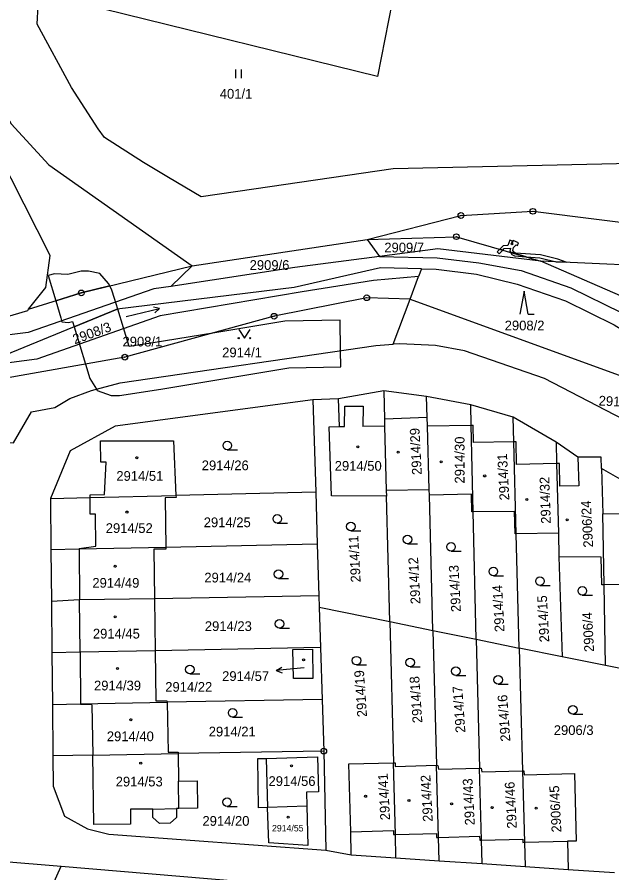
# Model space of a CAD drawing. Extents: x -644096 to -634268, y -1141430 to -1133463.
# Drawn here: x -640132.5 to -640028.5, y -1138278.2 to -1138128.6 of the extents above; entities that cross this region are included whole.
import ezdxf

# ---------------------------------------------------------------- set-up
doc = ezdxf.new("R2010")
doc.units = 0
for name, color, linetype in [('_CIVIL_CONSTRUCTION', 7, 'Continuous'), ('B_Hranice _3D', 7, 'Continuous'), ('M_Svah_Nasyp', 7, 'Continuous'), ('M_Svah_Zarez', 7, 'Continuous'), ('spodek_zarez', 7, 'Continuous'), ('svrsek_osa_sjezdy', 7, 'Continuous'), ('svrsek_osa_VRT', 7, 'Continuous'), ('svrsek_popisy_VRT', 7, 'Continuous'), ('terminal_VRT', 7, 'Continuous')]:
    doc.layers.add(name, color=color, linetype=linetype)

msp = doc.modelspace()

# ---------------------------------------------------------------- linework, layer by layer
at = {"layer": '_CIVIL_CONSTRUCTION'}
for centre, radius in [((-640054.9, -1138163.28), 0.5), ((-640042.31, -1138162.55), 0.5), ((-640042.31, -1138162.55), 0.0303), ((-640054.9, -1138163.28), 0.0303), ((-640055.7, -1138166.98), 0.5), ((-640055.7, -1138166.98), 0.0303), ((-640121.25, -1138176.81), 0.5), ((-640121.25, -1138176.81), 0.0303), ((-640071.36, -1138177.65), 0.5), ((-640071.36, -1138177.65), 0.0303), ((-640087.56, -1138180.89), 0.5), ((-640087.56, -1138180.89), 0.0303), ((-640113.65, -1138188.05), 0.5), ((-640113.65, -1138188.05), 0.0303), ((-640078.88, -1138256.92), 0.5), ((-640078.88, -1138256.92), 0.0303)]:
    msp.add_circle(centre, radius, dxfattribs=at)
at = {"layer": 'B_Hranice _3D'}
for points in [[(-640047.54, -1138168.57), (-640048.12, -1138169.17), (-640047.58, -1138169.32), (-640047.32, -1138169.05), (-640046.26, -1138168.98), (-640046.38, -1138169.52), (-640046.25, -1138169.71), (-640043.5, -1138170.5), (-640041.09, -1138170.68), (-640038.27, -1138171.36), (-640036.52, -1138171.44), (-640037.98, -1138170.92), (-640041.01, -1138170.18), (-640045.38, -1138169.86), (-640045.64, -1138169.7), (-640045.84, -1138169.4), (-640045.72, -1138168.85), (-640045.22, -1138168.43), (-640045.02, -1138168.52), (-640044.82, -1138168.06), (-640045.74, -1138167.66), (-640045.94, -1138168.12), (-640045.74, -1138168.21), (-640045.95, -1138168.39), (-640046.09, -1138168.28), (-640045.9, -1138167.79), (-640046.36, -1138167.61), (-640046.72, -1138168.51)], [(-640048.56, -1138169.63), (-640048.2, -1138169.97), (-640047.58, -1138169.32), (-640048.12, -1138169.17)], [(-640046.25, -1138169.71), (-640045.99, -1138170.07), (-640045.54, -1138170.35), (-640043.5, -1138170.5)], [(-640125.72, -1138178.2), (-640121.25, -1138176.81), (-640116.26, -1138175.59), (-640116.47, -1138175.15), (-640118, -1138173.44), (-640119.97, -1138172.99), (-640121.25, -1138172.99), (-640123.63, -1138173.58), (-640125.93, -1138173.45), (-640127.02, -1138173.76)], [(-640125.72, -1138178.2), (-640124.85, -1138181.16), (-640124.64, -1138181.89), (-640123.51, -1138181.98), (-640122.79, -1138181.8), (-640122.5, -1138182.77), (-640114.96, -1138179.68), (-640114.89, -1138179.67), (-640115.47, -1138177.78), (-640115.92, -1138176.32), (-640116.26, -1138175.59), (-640121.25, -1138176.81)], [(-640107.37, -1138193.62), (-640084.96, -1138189.92), (-640075.87, -1138189.76), (-640075.92, -1138186.9), (-640076.01, -1138181.58), (-640085.7, -1138181.76), (-640098.26, -1138183.83), (-640108.67, -1138185.54), (-640112.89, -1138186.21), (-640114.89, -1138179.67), (-640114.96, -1138179.68), (-640122.5, -1138182.77), (-640120.51, -1138189.27), (-640119.74, -1138191.8), (-640118.61, -1138193.62), (-640118.46, -1138193.86), (-640116.06, -1138194.76), (-640114.58, -1138194.76)]]:
    msp.add_lwpolyline(points, close=True, dxfattribs=at)
at = {"layer": 'M_Svah_Nasyp'}
for p, q in [((-640075.27, -1138200.17), (-640075.17, -1138196.61)), ((-640075.17, -1138196.61), (-640071.97, -1138196.59)), ((-640071.97, -1138196.59), (-640072.05, -1138200.14)), ((-640060.8, -1138198.57), (-640068.26, -1138198.9)), ((-640076.15, -1138200.18), (-640075.27, -1138200.17)), ((-640068.23, -1138200.1), (-640072.05, -1138200.14)), ((-640060.74, -1138200.07), (-640053.09, -1138199.95)), ((-640053.09, -1138199.95), (-640052.74, -1138199.94)), ((-640052.72, -1138202.98), (-640052.74, -1138199.94)), ((-640045.67, -1138202.84), (-640052.72, -1138202.98)), ((-640045.23, -1138202.83), (-640045.67, -1138202.84)), ((-640045.2, -1138206.83), (-640045.23, -1138202.83)), ((-640034.45, -1138205.52), (-640034.3, -1138210.54)), ((-640038.17, -1138206.63), (-640045.2, -1138206.83)), ((-640037.66, -1138206.62), (-640038.17, -1138206.63)), ((-640037.6, -1138210.57), (-640037.66, -1138206.62)), ((-640034.3, -1138210.54), (-640037.6, -1138210.57)), ((-640119.68, -1138215.48), (-640119.71, -1138212.58)), ((-640118.77, -1138215.47), (-640119.68, -1138215.48)), ((-640118.72, -1138221.1), (-640118.77, -1138215.47)), ((-640121.63, -1138221.48), (-640118.72, -1138221.1)), ((-640121.63, -1138221.48), (-640121.63, -1138221.63)), ((-640121.63, -1138221.63), (-640121.55, -1138230.49)), ((-640121.47, -1138239.64), (-640121.55, -1138230.49)), ((-640121.47, -1138239.64), (-640121.39, -1138248.65)), ((-640121.39, -1138248.79), (-640121.39, -1138248.65)), ((-640119.42, -1138248.8), (-640121.39, -1138248.79)), ((-640119.42, -1138248.8), (-640119.25, -1138257.62)), ((-640088.95, -1138258.18), (-640088.7, -1138266.77)), ((-640104.23, -1138266.94), (-640104.28, -1138262.19)), ((-640108.76, -1138267.04), (-640104.61, -1138266.97)), ((-640074.17, -1138271.02), (-640066.67, -1138270.8)), ((-640066.67, -1138270.8), (-640066.67, -1138271.5)), ((-640066.67, -1138271.5), (-640066.36, -1138271.49)), ((-640066.36, -1138271.49), (-640059.17, -1138271.29)), ((-640059.17, -1138271.29), (-640059.18, -1138272)), ((-640059.18, -1138272), (-640058.84, -1138271.99)), ((-640058.84, -1138271.99), (-640051.65, -1138271.8)), ((-640051.65, -1138271.8), (-640051.59, -1138272.49)), ((-640051.59, -1138272.49), (-640051.31, -1138272.48)), ((-640051.31, -1138272.48), (-640044.07, -1138272.31)), ((-640044.07, -1138272.31), (-640044.06, -1138272.87)), ((-640044.06, -1138272.87), (-640043.8, -1138272.85)), ((-640043.8, -1138272.85), (-640036.3, -1138272.68))]:
    msp.add_line(p, q, dxfattribs=at)
at = {"layer": 'M_Svah_Zarez'}
for centre in [(-640072.92, -1138203.72), (-640065.85, -1138204.67), (-640111.53, -1138205.62), (-640058.35, -1138206.33), (-640050.75, -1138208.82), (-640043.39, -1138212.91), (-640113.27, -1138215.12), (-640036.34, -1138216.47), (-640115.33, -1138224.61), (-640115.33, -1138233.43), (-640082.39, -1138240.94), (-640114.93, -1138242.46), (-640112.61, -1138251.42), (-640110.87, -1138259.03), (-640084.5, -1138259.5), (-640071.55, -1138264.82), (-640063.98, -1138265.56), (-640056.52, -1138266.12), (-640049.45, -1138266.8), (-640041.77, -1138266.91), (-640085.08, -1138268.46)]:
    msp.add_circle(centre, 0.175, dxfattribs=at)
at = {"layer": 'spodek_zarez'}
msp.add_circle((-638683.07, -1137056.85), 1378.08, dxfattribs=at)
at = {"layer": 'svrsek_osa_sjezdy'}
for p, q in [((-640094.25, -1138139.27), (-640094.25, -1138137.77)), ((-640093.25, -1138139.27), (-640093.25, -1138137.77)), ((-640043.87, -1138176.51), (-640044.62, -1138180.51)), ((-640043.12, -1138180.51), (-640043.87, -1138176.51)), ((-640107.57, -1138179.56), (-640108.63, -1138179.29)), ((-640113.41, -1138180.91), (-640107.57, -1138179.56)), ((-640107.57, -1138179.56), (-640108.41, -1138180.27)), ((-640043.12, -1138180.51), (-640042.12, -1138180.51)), ((-640095.73, -1138204.24), (-640093.98, -1138204.24)), ((-640086.99, -1138217.07), (-640085.24, -1138217.07)), ((-640074.15, -1138218.38), (-640072.4, -1138218.38)), ((-640064.24, -1138220.67), (-640062.49, -1138220.67)), ((-640056.63, -1138221.94), (-640054.88, -1138221.94)), ((-640086.79, -1138226.73), (-640085.04, -1138226.73)), ((-640049.23, -1138226.28), (-640047.48, -1138226.28)), ((-640041.08, -1138227.97), (-640039.33, -1138227.97)), ((-640033.68, -1138229.66), (-640031.93, -1138229.66)), ((-640086.59, -1138235.41), (-640084.84, -1138235.41)), ((-640073.16, -1138241.85), (-640071.41, -1138241.85)), ((-640063.78, -1138242.16), (-640062.03, -1138242.16)), ((-640102.28, -1138243.41), (-640100.53, -1138243.41)), ((-640055.81, -1138243.68), (-640054.06, -1138243.68)), ((-640048.41, -1138245.21), (-640046.66, -1138245.21)), ((-640094.8, -1138250.97), (-640093.05, -1138250.97)), ((-640035.34, -1138250.47), (-640033.59, -1138250.47)), ((-640095.78, -1138266.59), (-640094.03, -1138266.59))]:
    msp.add_line(p, q, dxfattribs=at)
msp.add_lwpolyline([(-640093.74, -1138183.23), (-640092.74, -1138184.73), (-640091.74, -1138183.23)], dxfattribs=at)
for centre, radius in [((-640093.74, -1138184.73), 0.1), ((-640091.74, -1138184.73), 0.1), ((-640095.73, -1138203.49), 0.75), ((-640086.99, -1138216.32), 0.75), ((-640074.15, -1138217.63), 0.75), ((-640064.24, -1138219.92), 0.75), ((-640056.63, -1138221.19), 0.75), ((-640086.79, -1138225.98), 0.75), ((-640049.23, -1138225.53), 0.75), ((-640041.08, -1138227.22), 0.75), ((-640033.68, -1138228.91), 0.75), ((-640086.59, -1138234.66), 0.75), ((-640073.16, -1138241.1), 0.75), ((-640063.78, -1138241.41), 0.75), ((-640102.28, -1138242.66), 0.75), ((-640055.81, -1138242.93), 0.75), ((-640048.41, -1138244.46), 0.75), ((-640094.8, -1138250.22), 0.75), ((-640035.34, -1138249.72), 0.75), ((-640095.78, -1138265.84), 0.75)]:
    msp.add_circle(centre, radius, dxfattribs=at)
at = {"layer": 'svrsek_popisy_VRT'}
for p, q in [((-640087.17, -1138242.85), (-640086.22, -1138242.25)), ((-640084.18, -1138242.54), (-640087.17, -1138242.85)), ((-640087.17, -1138242.85), (-640086.12, -1138243.25)), ((-640082.31, -1138242.35), (-640084.18, -1138242.54))]:
    msp.add_line(p, q, dxfattribs=at)
at = {"layer": 'terminal_VRT'}
for p, q in [((-640101.86, -1138172.06), (-640071.28, -1138167.46)), ((-640071.28, -1138167.46), (-640069.11, -1138170.45)), ((-640101.86, -1138172.06), (-640105.62, -1138175.67)), ((-640061.8, -1138172.6), (-640068.96, -1138172.45)), ((-640061.8, -1138172.6), (-640062.3, -1138173.93)), ((-640062.3, -1138173.93), (-640070.2, -1138174.64)), ((-640063.78, -1138177.89), (-640062.3, -1138173.93)), ((-640066.74, -1138185.8), (-640063.78, -1138177.89)), ((-640063.78, -1138177.89), (-640025.5, -1138191.85)), ((-640068.39, -1138193.94), (-640076.3, -1138195.32)), ((-640060.89, -1138194.94), (-640068.39, -1138193.94)), ((-640076.3, -1138195.32), (-640080.78, -1138195.53)), ((-640080.78, -1138195.53), (-640080.28, -1138211.67)), ((-640053.17, -1138196.36), (-640060.89, -1138194.94)), ((-640045.78, -1138198.51), (-640053.17, -1138196.36)), ((-640038.26, -1138202.9), (-640045.78, -1138198.51)), ((-640030.32, -1138207.49), (-640030.1, -1138215.44)), ((-640008.99, -1138219.81), (-640030.32, -1138207.49)), ((-640119.71, -1138212.58), (-640104.71, -1138212.23)), ((-640080.28, -1138211.67), (-640104.71, -1138212.23)), ((-640080.28, -1138211.67), (-640080, -1138220.72)), ((-640060.47, -1138211.26), (-640067.94, -1138211.35)), ((-640067.94, -1138211.35), (-640067.91, -1138212.35)), ((-640067.34, -1138234.28), (-640067.91, -1138212.35)), ((-640060.4, -1138212.17), (-640060.47, -1138211.26)), ((-640059.79, -1138235.82), (-640060.4, -1138212.17)), ((-640126.64, -1138212.74), (-640119.71, -1138212.58)), ((-640126.64, -1138212.74), (-640126.55, -1138221.74)), ((-640052.26, -1138237.35), (-640052.75, -1138215.1)), ((-640029.89, -1138227.85), (-640030.1, -1138215.44)), ((-640037.86, -1138218.81), (-640045.25, -1138218.92)), ((-640044.73, -1138238.89), (-640045.25, -1138218.92)), ((-640037.86, -1138218.81), (-640037.77, -1138222.97)), ((-640080, -1138220.72), (-640106.49, -1138221.3)), ((-640080, -1138220.72), (-640079.72, -1138229.77)), ((-640126.55, -1138221.74), (-640126.47, -1138230.74)), ((-640037.77, -1138222.97), (-640037.19, -1138240.42)), ((-640029.65, -1138241.96), (-640029.89, -1138227.85)), ((-640079.72, -1138229.77), (-640108.46, -1138230.31)), ((-640079.72, -1138229.77), (-640079.66, -1138231.78)), ((-640126.47, -1138230.74), (-640126.38, -1138239.74)), ((-640108.46, -1138230.31), (-640108.35, -1138239.39)), ((-640079.66, -1138231.78), (-640067.34, -1138234.28)), ((-640079.66, -1138231.78), (-640079.44, -1138238.82)), ((-640067.34, -1138234.28), (-640066.69, -1138258.96)), ((-640067.34, -1138234.28), (-640059.79, -1138235.82)), ((-640059.79, -1138235.82), (-640052.26, -1138237.35)), ((-640059.79, -1138235.82), (-640059.17, -1138259.4)), ((-640052.26, -1138237.35), (-640044.73, -1138238.89)), ((-640052.26, -1138237.35), (-640051.65, -1138259.91)), ((-640079.44, -1138238.82), (-640108.35, -1138239.39)), ((-640079.44, -1138238.82), (-640079.16, -1138247.87)), ((-640037.19, -1138240.42), (-640044.73, -1138238.89)), ((-640044.73, -1138238.89), (-640044.14, -1138260.35)), ((-640126.38, -1138239.74), (-640126.3, -1138248.74)), ((-640029.65, -1138241.96), (-640037.19, -1138240.42)), ((-640022.84, -1138243.35), (-640029.65, -1138241.96)), ((-640079.16, -1138247.87), (-640106.27, -1138248.37)), ((-640079.16, -1138247.87), (-640078.88, -1138256.92)), ((-640126.3, -1138248.74), (-640126.21, -1138257.74)), ((-640078.88, -1138256.92), (-640104.34, -1138257.34)), ((-640078.88, -1138256.92), (-640078.52, -1138274.23)), ((-640119.25, -1138257.62), (-640126.21, -1138257.74)), ((-640119.25, -1138257.62), (-640104.34, -1138257.34)), ((-640081.82, -1138266.53), (-640088.7, -1138266.77)), ((-640078.52, -1138274.23), (-640074.07, -1138275.04)), ((-640074.07, -1138275.04), (-640066.25, -1138275.57)), ((-640066.25, -1138275.57), (-640058.73, -1138276.08)), ((-640058.73, -1138276.08), (-640051.2, -1138276.59)), ((-640051.2, -1138276.59), (-640043.68, -1138277.1)), ((-640124.76, -1138277.05), (-640083.27, -1138280.51)), ((-640043.68, -1138277.1), (-640036.16, -1138277.6)), ((-640036.16, -1138277.6), (-640028.04, -1138278.15))]:
    msp.add_line(p, q, dxfattribs=at)
for points in [[(-639964.57, -1138155.72), (-639970.93, -1138156.51), (-639981.92, -1138158.02), (-640012.66, -1138153.48), (-640025.08, -1138154.19), (-640066.74, -1138155.12), (-640091.07, -1138158.68), (-640100.29, -1138160), (-640106.04, -1138156.61), (-640110.39, -1138154.04), (-640117.22, -1138149.62), (-640118.33, -1138148.11), (-640122.99, -1138140.9), (-640128.97, -1138129.83), (-640128.12, -1138113.45), (-640129.91, -1138106.89), (-640135.07, -1138095.63), (-640136.46, -1138093.31)], [(-640125.7, -1138099.66), (-640125.1, -1138103.21), (-640122.95, -1138109.83), (-640120.35, -1138113.31), (-640115.86, -1138115), (-640114.4, -1138107.51), (-640065.64, -1138119.33), (-640069.46, -1138138.97), (-640117.31, -1138127.21), (-640116, -1138120.49), (-640123.3, -1138118.01), (-640129.85, -1138099.16), (-640131.13, -1138096.38)], [(-640269.74, -1138181.24), (-640284.28, -1138177.7), (-640283.65, -1138163.14), (-640278.43, -1138154.54), (-640260.81, -1138144.4), (-640250.28, -1138126.64), (-640249.95, -1138111.05), (-640244.3, -1138108.64), (-640240.85, -1138108.4), (-640180.48, -1138113.95), (-640156.4, -1138108.35), (-640147.57, -1138118.28), (-640140.23, -1138135.35), (-640133.49, -1138147.23), (-640126.91, -1138154.41), (-640101.86, -1138172.06)], [(-640130.46, -1138179.68), (-640127.48, -1138175.86), (-640126.67, -1138170.26), (-640149.51, -1138125.25), (-640154.45, -1138122.4), (-640159.15, -1138122.47), (-640239.14, -1138123.66), (-640248.63, -1138129.89), (-640258.75, -1138143.28), (-640266, -1138158.68), (-640267.64, -1138164.01), (-640267.29, -1138175.17), (-640266.27, -1138180.09)], [(-640071.28, -1138167.46), (-640054.9, -1138163.28), (-640042.31, -1138162.55), (-639994.57, -1138168.5), (-639967.15, -1138169.36), (-639952.57, -1138168.47), (-639950.23, -1138170.07), (-639941.74, -1138175.48)], [(-640071.28, -1138167.46), (-640055.7, -1138166.98), (-640040.94, -1138171.24)], [(-640069.11, -1138170.45), (-640083.93, -1138172.37), (-640105.62, -1138175.67)], [(-640040.94, -1138171.24), (-640058.94, -1138169.13), (-640069.11, -1138170.45)], [(-640069.11, -1138170.45), (-640059.05, -1138170.66), (-640051.78, -1138171.58), (-640044.37, -1138172.92), (-640035.68, -1138175.94), (-640026.91, -1138180.25), (-640018.62, -1138185.33), (-640008.1, -1138194.3), (-639989.34, -1138210.79), (-639965.8, -1138213.29), (-639950.45, -1138211.57), (-639945.86, -1138213.03), (-639937.34, -1138221.26), (-639936.21, -1138221.49), (-639933.84, -1138221.84), (-639891.59, -1138218.9), (-639875.06, -1138222.44), (-639841.83, -1138231.14), (-639830.5, -1138233.25), (-639820.91, -1138233.83), (-639809.11, -1138234.17), (-639758.74, -1138238.27), (-639748.88, -1138238.87), (-639700.55, -1138249.98)], [(-639944.04, -1138182.89), (-639944.02, -1138179.6), (-639953.15, -1138175.84), (-639964.62, -1138174.37), (-639980.56, -1138175.67), (-640015.24, -1138172.43), (-640040.94, -1138171.24)], [(-639991.53, -1138205.59), (-640001.69, -1138195.34), (-640015.51, -1138183.62), (-640025.66, -1138177.9), (-640040.94, -1138171.24)], [(-640068.96, -1138172.45), (-640084.04, -1138175.86), (-640114.96, -1138179.68), (-640134.56, -1138187.72), (-640175.26, -1138190.33)], [(-640130.46, -1138179.68), (-640121.25, -1138176.81), (-640101.86, -1138172.06)], [(-640061.8, -1138172.6), (-640059.2, -1138172.66), (-640052.15, -1138173.55), (-640045.06, -1138175.27), (-640036.63, -1138178.2), (-640028.09, -1138182.4), (-640020.06, -1138187.32), (-640009.69, -1138196.16), (-639990.18, -1138212.71)], [(-640070.2, -1138174.64), (-640082.65, -1138176.64), (-640107.48, -1138180.83), (-640129.05, -1138188.37), (-640149.86, -1138191.12), (-640169.26, -1138191.54)], [(-640105.62, -1138175.67), (-640108.55, -1138176.11), (-640130.53, -1138183.72), (-640150.56, -1138186.24), (-640169.17, -1138186.77), (-640173.34, -1138185.75), (-640178.15, -1138184.55)], [(-640063.78, -1138177.89), (-640071.36, -1138177.65), (-640087.56, -1138180.89), (-640113.65, -1138188.05), (-640136.4, -1138192.08)], [(-640165.29, -1138182.95), (-640139.5, -1138182.51), (-640130.6, -1138179.86), (-640130.46, -1138179.68)], [(-640136.12, -1138202.84), (-640133.1, -1138203), (-640129.94, -1138197.63), (-640125.85, -1138196.87), (-640123.25, -1138195.28), (-640119.47, -1138193.85), (-640114.48, -1138192.52), (-640069.79, -1138186.01), (-640066.74, -1138185.8)], [(-639993.56, -1138219.33), (-640026.5, -1138198.95), (-640040.31, -1138191.76), (-640054.27, -1138186.91), (-640059.37, -1138186.03), (-640065.6, -1138185.72), (-640066.74, -1138185.8)], [(-640068.39, -1138193.94), (-640068.26, -1138198.9), (-640068.23, -1138200.1), (-640067.94, -1138211.35)], [(-640080.78, -1138195.53), (-640115.31, -1138200.13), (-640123.18, -1138204.41), (-640126.64, -1138212.74)], [(-640067.91, -1138212.35), (-640077.54, -1138212.26), (-640077.94, -1138200.2), (-640076.15, -1138200.18), (-640076.3, -1138195.32)], [(-640060.47, -1138211.26), (-640060.74, -1138200.07), (-640060.8, -1138198.57), (-640060.89, -1138194.94)], [(-640052.75, -1138215.1), (-640053.09, -1138199.95), (-640053.17, -1138196.36)], [(-640045.25, -1138218.92), (-640045.67, -1138202.84), (-640045.78, -1138198.51)], [(-640119.71, -1138212.58), (-640119.72, -1138212.11), (-640117.21, -1138212.04), (-640116.91, -1138206.39), (-640117.82, -1138206.41), (-640117.91, -1138202.7), (-640105.12, -1138202.66), (-640104.71, -1138212.23)], [(-640030.32, -1138207.49), (-640030.37, -1138205.54), (-640034.45, -1138205.52), (-640038.26, -1138202.9)], [(-640038.26, -1138202.9), (-640038.17, -1138206.63), (-640037.86, -1138218.81)], [(-640104.71, -1138212.23), (-640104.7, -1138212.56), (-640106.62, -1138212.66), (-640106.49, -1138221.3)], [(-640052.75, -1138215.1), (-640052.98, -1138215.1), (-640053.05, -1138212), (-640060.4, -1138212.17)], [(-640045.25, -1138218.92), (-640045.44, -1138218.92), (-640045.52, -1138215.04), (-640052.75, -1138215.1)], [(-640030.1, -1138215.44), (-640022.62, -1138215.35), (-640022.56, -1138218.82), (-640018.58, -1138218.76), (-640018.41, -1138227.55), (-640022.4, -1138227.72), (-640029.89, -1138227.85)], [(-640106.49, -1138221.3), (-640121.63, -1138221.63), (-640126.55, -1138221.74)], [(-640106.49, -1138221.3), (-640106.49, -1138221.61), (-640108.56, -1138221.61), (-640108.46, -1138230.31)], [(-640029.89, -1138227.85), (-640030.25, -1138227.86), (-640030.37, -1138222.99), (-640037.77, -1138222.97)], [(-640108.46, -1138230.31), (-640121.55, -1138230.49), (-640126.47, -1138230.74)], [(-640084.19, -1138244.25), (-640084.3, -1138239.15), (-640080.85, -1138239.11), (-640080.79, -1138244.22), (-640084.19, -1138244.25)], [(-640108.35, -1138239.39), (-640121.47, -1138239.64), (-640126.38, -1138239.74)], [(-640108.35, -1138239.39), (-640108.25, -1138248.11), (-640106.28, -1138248.12), (-640106.27, -1138248.37)], [(-640126.3, -1138248.74), (-640121.39, -1138248.65), (-640106.27, -1138248.37)], [(-640106.27, -1138248.37), (-640106.06, -1138257.1), (-640104.34, -1138257.11), (-640104.34, -1138257.34)], [(-640126.21, -1138257.74), (-640126.15, -1138263.03), (-640124.21, -1138268.31), (-640120.19, -1138270.53), (-640116.43, -1138271.45), (-640078.52, -1138274.23)], [(-640104.34, -1138257.34), (-640104.28, -1138262.19), (-640100.98, -1138262.14), (-640100.96, -1138266.9), (-640104.23, -1138266.94), (-640104.61, -1138266.97), (-640104.63, -1138268.51), (-640105.7, -1138269.53), (-640107.59, -1138269.55), (-640108.74, -1138268.54), (-640108.76, -1138267.04), (-640112.68, -1138267.07), (-640112.68, -1138269.69), (-640119.05, -1138269.77), (-640119.25, -1138257.62)], [(-640088.7, -1138266.77), (-640090.27, -1138266.81), (-640090.4, -1138258.22), (-640088.95, -1138258.18), (-640079.95, -1138257.92), (-640079.77, -1138264.03), (-640081.9, -1138264.11), (-640081.82, -1138266.53)], [(-640074.07, -1138275.04), (-640074.17, -1138271.02), (-640074.48, -1138259.16), (-640066.69, -1138258.96)], [(-640066.69, -1138258.96), (-640066.38, -1138258.95), (-640066.37, -1138259.61), (-640059.17, -1138259.4)], [(-640066.25, -1138275.57), (-640066.36, -1138271.49), (-640066.69, -1138258.96)], [(-640058.73, -1138276.08), (-640058.84, -1138271.99), (-640059.17, -1138259.4)], [(-640059.17, -1138259.4), (-640058.91, -1138259.41), (-640058.82, -1138260.06), (-640051.65, -1138259.91)], [(-640051.65, -1138259.91), (-640051.37, -1138259.9), (-640051.27, -1138260.51), (-640044.14, -1138260.35)], [(-640051.2, -1138276.59), (-640051.31, -1138272.48), (-640051.65, -1138259.91)], [(-640044.14, -1138260.35), (-640043.89, -1138260.36), (-640043.86, -1138261.07), (-640035.02, -1138260.82), (-640034.78, -1138272.66), (-640036.3, -1138272.68), (-640036.16, -1138277.6)], [(-640044.14, -1138260.35), (-640043.8, -1138272.85), (-640043.68, -1138277.1)], [(-640081.82, -1138266.53), (-640081.64, -1138273.42), (-640088.5, -1138272.94), (-640088.7, -1138266.77)], [(-640181.58, -1138272.32), (-640180.38, -1138272.42), (-640124.76, -1138277.05)], [(-640140.16, -1138309.96), (-640129.55, -1138287.72), (-640124.76, -1138277.05)]]:
    msp.add_lwpolyline(points, dxfattribs=at)

# ---------------------------------------------------------------- texts
at = {"layer": 'svrsek_osa_VRT'}
for s, height, p in [('401/1', 1.7, (-640097.05, -1138142.85)), ('2909/7', 1.7, (-640068.29, -1138169.73)), ('2909/6', 1.7, (-640091.83, -1138172.79)), ('2908/2', 1.7, (-640047.25, -1138183.36)), ('2908/1', 1.7, (-640114.05, -1138186.17)), ('2914/1', 1.7, (-640096.63, -1138188.07)), ('2914/26', 1.7, (-640100.2, -1138207.81)), ('2914/50', 1.7, (-640076.96, -1138207.9)), ('2914/51', 1.7, (-640115.13, -1138209.66)), ('2914/25', 1.7, (-640099.85, -1138217.77)), ('2914/52', 1.7, (-640116.98, -1138218.78)), ('2914/24', 1.7, (-640099.75, -1138227.43)), ('2914/49', 1.7, (-640119.32, -1138228.35)), ('2914/23', 1.7, (-640099.66, -1138235.92)), ('2914/45', 1.7, (-640119.23, -1138237.23)), ('2914/57', 1.7, (-640096.64, -1138244.65)), ('2914/39', 1.7, (-640119.03, -1138246.3)), ('2914/22', 1.7, (-640106.58, -1138246.54)), ('2914/21', 1.7, (-640098.98, -1138254.35)), ('2906/3', 1.7, (-640038.67, -1138254.1)), ('2914/40', 1.7, (-640116.79, -1138255.18)), ('2914/53', 1.7, (-640115.24, -1138263.09)), ('2914/56', 1.7, (-640088.53, -1138263.01)), ('2914/20', 1.7, (-640100.08, -1138269.97)), ('2914/55', 1.14, (-640087.92, -1138270.96))]:
    msp.add_text(s, height=height, dxfattribs=at).set_placement(p)
for s, rotation, p in [('2908/3', 20, (-640122.39, -1138185.81)), ('2914/58', 357, (-640030.86, -1138196.48)), ('2914/29', 93, (-640061.73, -1138208.59)), ('2914/30', 90, (-640054.27, -1138210.14)), ('2914/31', 93, (-640046.43, -1138213.04)), ('2914/32', 92, (-640039.18, -1138217.14)), ('2906/24', 93, (-640031.78, -1138221.28)), ('2914/11', 93, (-640072.42, -1138227.38)), ('2914/12', 93, (-640061.97, -1138231.18)), ('2914/13', 93, (-640054.9, -1138232.55)), ('2914/14', 93, (-640047.28, -1138236.05)), ('2914/15', 93, (-640039.45, -1138237.85)), ('2906/4', 93, (-640031.62, -1138239.54)), ('2914/19', 94, (-640071.3, -1138250.91)), ('2914/18', 94, (-640061.63, -1138251.96)), ('2914/17', 94, (-640054.11, -1138253.66)), ('2914/16', 94, (-640046.25, -1138255.19)), ('2914/41', 93, (-640067.28, -1138268.95)), ('2914/42', 93, (-640059.82, -1138269.23)), ('2914/43', 93, (-640052.47, -1138269.85)), ('2914/46', 93, (-640045.12, -1138270.42)), ('2906/45', 93, (-640037.33, -1138271.09))]:
    msp.add_text(s, height=1.7, rotation=rotation, dxfattribs=at).set_placement(p)

doc.saveas('drawing.dxf')
